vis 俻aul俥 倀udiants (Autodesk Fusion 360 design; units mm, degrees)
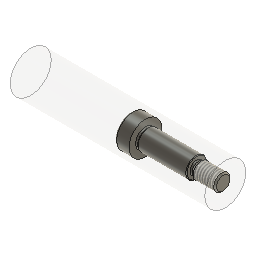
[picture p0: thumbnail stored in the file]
sketch "Esquisse1" plane through (0, 0, 0) normal (0, 0, 1) x axis (1, 0, 0)
  line L1 (-45, 0) -> (0, 0)
  line L2 (-45, 8) -> (-45, 0)
  line L3 (-38, 8) -> (-45, 8)
  line L4 (-38, 4.75) -> (-38, 8)
  line L5 (-37, 4.75) -> (-38, 4.75)
  line L6 (-36.567, 5) -> (-37, 4.75)
  line L7 (-13, 5) -> (-36.567, 5)
  line L8 (-13, 3.2333) -> (-13, 5)
  line L9 (-12, 3.2333) -> (-13, 3.2333)
  line L10 (-10.672, 4) -> (-12, 3.2333)
  line L11 (-0.7667, 4) -> (-10.672, 4)
  line L12 (0, 3.2333) -> (-0.7667, 4)
  line L13 (0, 0) -> (0, 3.2333)
  point P1 (0, 0)
  point P2 (0, 0)
  point P10 (-13, 3.2333)
  point P11 (-12, 3.2333)
  point P6 (-38, 4.75)
  point P7 (-37, 4.75)
  point P4 (-45, 8)
  point P5 (-38, 8)
  coincident P1 P2
  horizontal L1
  perpendicular L1 L2
  perpendicular L2 L3
  perpendicular L3 L4
  perpendicular L4 L5
  perpendicular L4 L7
  perpendicular L7 L8
  perpendicular L8 L9
  perpendicular L1 L13
  dimension "d1" angle L12 L13 = 45 (= "Angular Dimension-2")
  dimension "d2" = 8
  dimension "d3" = 10
  dimension "d4" = 16
  dimension "d5" distance L8 L13 = 13
  dimension "d6" = 6.4665 (= "d2 - ( 1.2268 * 1.25 ) * 1 mm")
  dimension "d8" distance P10 P11 = 1
  dimension "d9" angle L9 L10 = 30 (= "Angular Dimension-3")
  dimension "d11" = 6.4665 (= "d6")
  dimension "d12" distance L4 L8 = 25
  dimension "d13" distance P6 P7 = 1
  dimension "d14" angle L5 L6 = 30 (= "Angular Dimension-4")
  dimension "d15" distance P4 P5 = 7
  dimension "d16" = 9.5 (= "d3 - 0.5 mm")
revolve "Révolution1" sketch "Esquisse1"
fillet "Congé" radius 1
chamfer "Chanfrein" distance 0.3
thread "Filetage"
sketch "Esquisse2" plane through (0, 0, 0) normal (0, 0, 1) x axis (1, 0, 0)
  line L1 (-10.788, 3.933) -> (-10.788, -3.933)
  line L2 (-5.5219, 0) -> (0, 0)
  line L3 (1, 10) -> (1, 0)
  line L4 (-94, 10) -> (1, 10)
  line L5 (-94, 0) -> (-94, 10)
  line L6 (1, 0) -> (-94, 0)
  point P1 (0, 0)
  point P4 (0, 0)
  point P7 (1, 10)
  point P8 (-94, 10)
  coincident P1 P4
  perpendicular L1 L2
  vertical L3
  perpendicular L3 L4
  perpendicular L2 L5
  perpendicular L1 L6
  coincident P1 L6
  dimension "d21" distance P1 L3 = 1
  dimension "d22" distance P7 P8 = 95 (= "d5 + d12 + d15 + 50 mm")
  dimension "d23" distance L4 L6 = 10 (= "d4 / 2 + 2 mm")
component_from_bodies "Corps->Comp"
revolve "Révolution2" sketch "Esquisse2"
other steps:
base_feature "Fonction de base"
create_component "CreateComponent1"
remove_body "RemoveBody1"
